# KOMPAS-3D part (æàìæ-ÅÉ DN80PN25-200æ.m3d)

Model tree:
1. Объединить компоненты:1  (labels: СЕНС-ПР DN80PN25-200С)

Referenced files in D:\Савин\!СЕНСОР\3D для заказчика\!Новый перечень\СЕНС-ПР\2. СЕНС-ПР-200С\DN80\: СЕНС-ПР DN80PN25-200С.a3d
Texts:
  СЕНС-ПР DN80PN25-200С
  ООО НПП Сенсор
